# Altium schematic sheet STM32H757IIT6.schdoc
size 292 x 304 mm
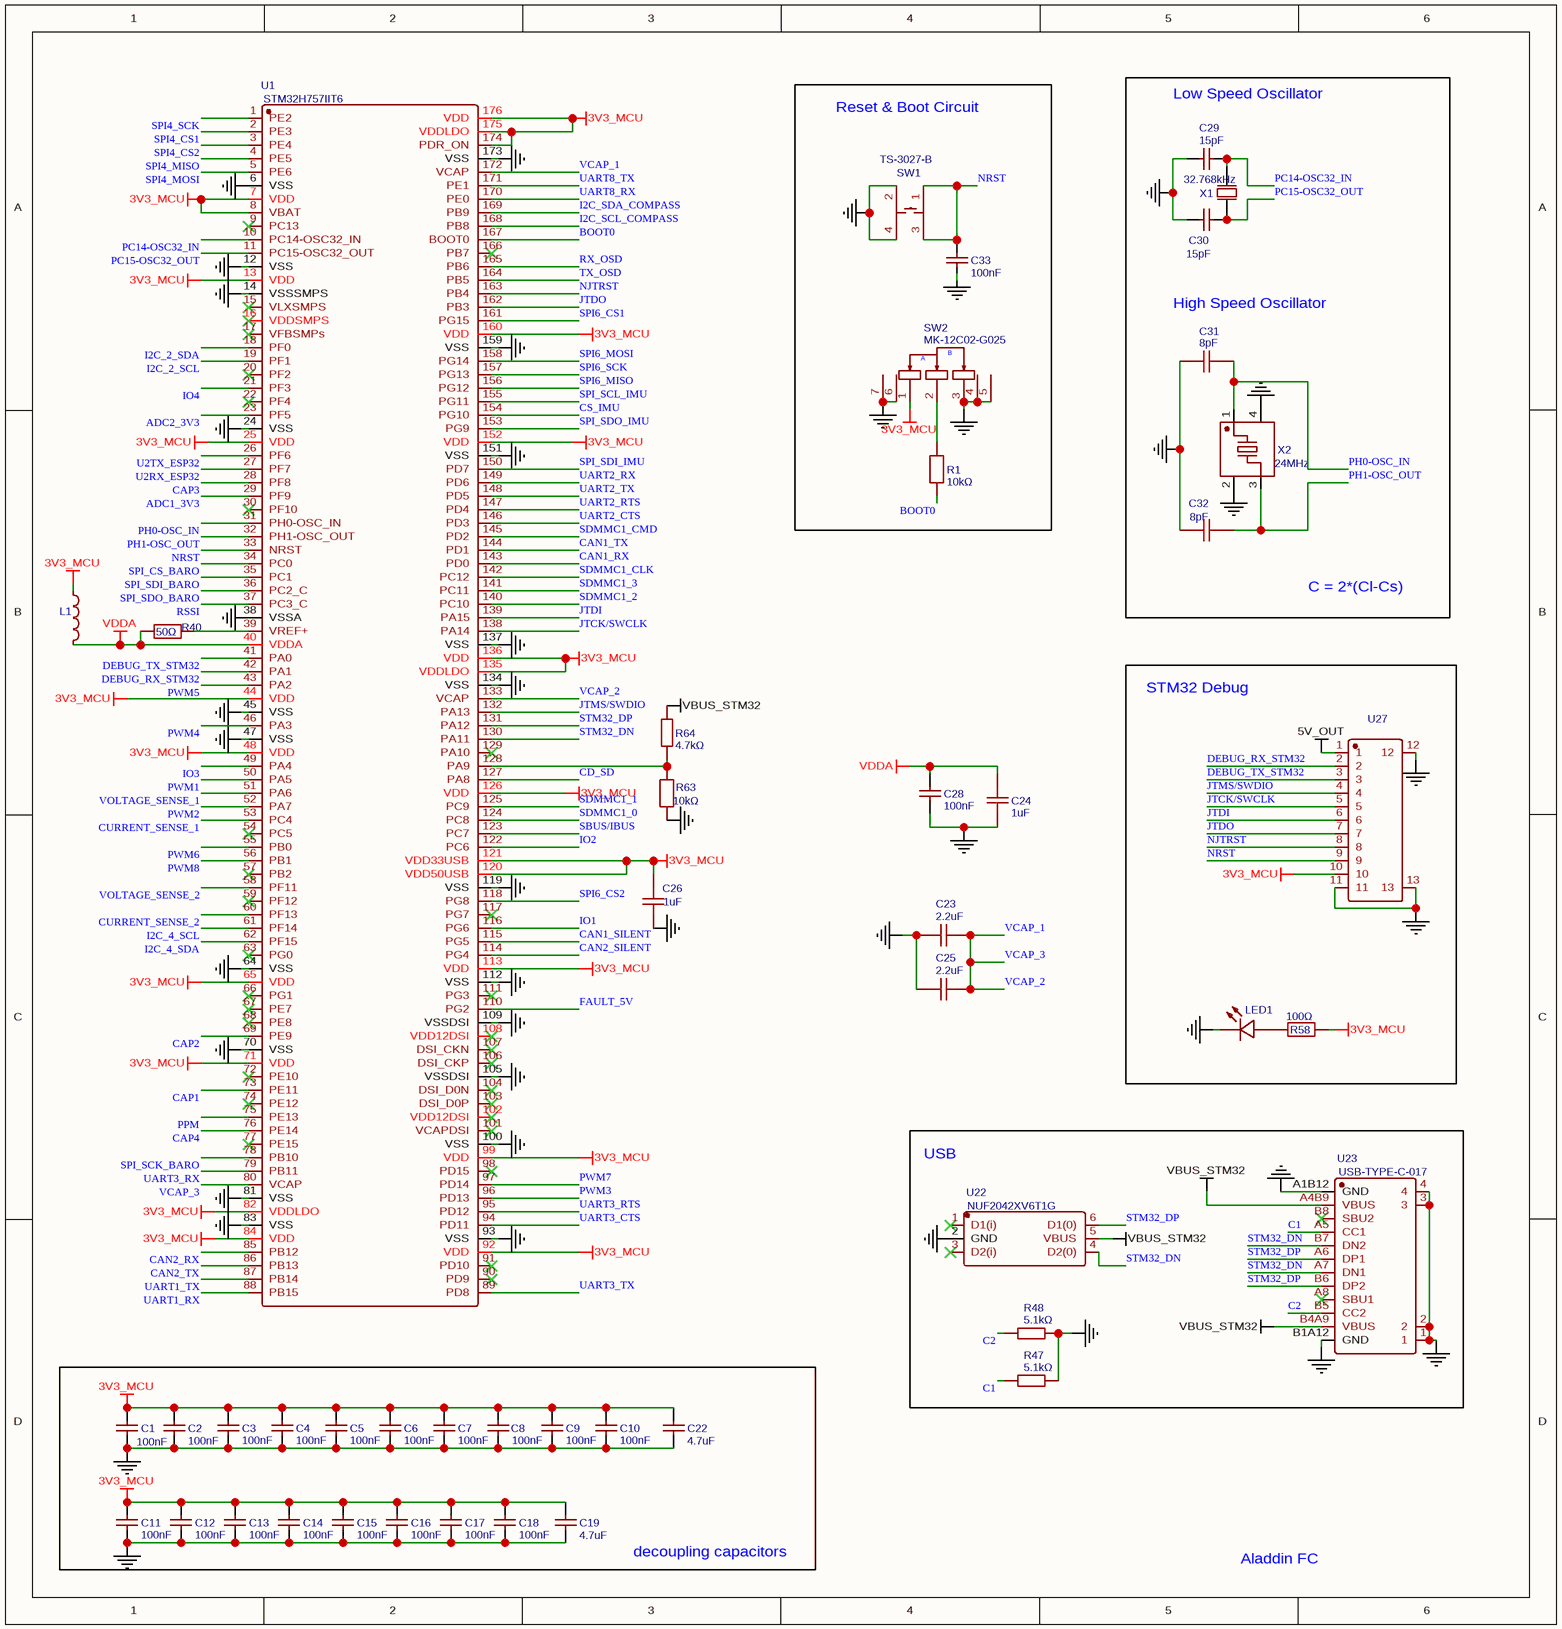
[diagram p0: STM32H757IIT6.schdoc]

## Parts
C1  100nF  [C0805]
C2  100nF  [C0805]
C3  100nF  [C0805]
C4  100nF  [C0805]
C5  100nF  [C0805]
C6  100nF  [C0805]
C7  100nF  [C0805]
C8  100nF  [C0805]
C9  100nF  [C0805]
C10  100nF  [C0805]
C11  100nF  [C0805]
C12  100nF  [C0805]
C13  100nF  [C0805]
C14  100nF  [C0805]
C15  100nF  [C0805]
C16  100nF  [C0805]
C17  100nF  [C0805]
C18  100nF  [C0805]
C19  4.7uF  [C0805]
C22  4.7uF  [C0805]
C23  2.2uF  [C0805]
C24  1uF  [C0805]
C25  2.2uF  [C0805]
C26  1uF  [C0805]
C28  100nF  [C0805]
C29  15pF  [C0603]
C30  15pF  [C0603]
C31  8pF  [C0805]
C32  8pF  [C0805]
C33  100nF  [C0805]
L1  FCM1005KF-601T03  [L0402]  (value not drawn)
LED1  SZYY0805B  [LED0805-R-RD_BLUE]  (value not drawn)
R1  10kΩ  [R0805]
R40  50Ω  [R0805]
R47  5.1kΩ  [R0402]
R48  5.1kΩ  [R0402]
R58  100Ω  [R0603]
R63  10kΩ  [R0805]
R64  4.7kΩ  [R0805]
SW1  TS-3027-B  [SW-SMD_4P-L3.0-W2.8-P1.65-TL_GT-TS171A-H014-L1]
SW2  MK-12C02-G025  [SW-SMD_MK-12C02-G025]
U1  STM32H757IIT6  [LQFP-176_L24.0-W24.0-P0.50-LS26.0-BL]
U22  NUF2042XV6T1G  [SOT-563_L1.6-W1.2-P0.50-LS1.6-TL]
U23  USB-TYPE-C-017  [USB-TYPE-C-SMD_C9900008089_ALA1]
U27  A1257WR-S-11P  [CONN-SMD_A1257WR-S-11P]  (value not drawn)
X1  32.768kHz  [OSC-SMD_2P-L3.2-W1.5]
X2  24MHz  [OSC-SMD_4P-L2.0-W1.6-BL]

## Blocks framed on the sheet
Reset & Boot Circuit: C33 R1 SW1 SW2
STM32 Debug: LED1 R58 U27
USB: R47 R48 U22 U23
decoupling capacitors: C1-C19 C22

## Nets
3V3_MCU: C1.1 C2.2 C3.2 C4.2 C5.2 C6.2 C7.1 C8.2 C9.2 C10.2 C11.1 C12.2 C13.2 C14.2 C15.2 C16.2 C17.1 C18.2 C19.2 C22.2 C26.1 L1.1 R58.2 SW2.1 U1.7(VDD) U1.8(VBAT) U1.13(VDD) U1.25(VDD) U1.44(VDD) U1.48(VDD) U1.65(VDD) U1.71(VDD) U1.82(VDDLDO) U1.84(VDD) U1.92(VDD) U1.99(VDD) U1.113(VDD) U1.120(VDD50USB) U1.121(VDD33USB) U1.126(VDD) U1.135(VDDLDO) U1.136(VDD) U1.152(VDD) U1.160(VDD) U1.174(PDR_ON) U1.175(VDDLDO) U1.176(VDD) U27.10
5V_OUT: U27.1
GND: C1.2 C2.1 C3.1 C4.1 C5.1 C6.1 C7.2 C8.1 C9.1 C10.1 C11.2 C12.1 C13.1 C14.1 C15.1 C16.1 C17.2 C18.1 C19.1 C22.1 C23.1 C24.2 C25.1 C26.2 C28.2 C29.1 C30.1 C31.1 C32.1 C33.1 LED1.2(-) R47.2 R48.2 R63.1 SW1.2 SW1.4 SW2.3 SW2.4 SW2.5 SW2.6 SW2.7 U1.6(VSS) U1.12(VSS) U1.14(VSSSMPS) U1.24(VSS) U1.38(VSSA) U1.45(VSS) U1.47(VSS) U1.64(VSS) U1.70(VSS) U1.81(VSS) U1.83(VSS) U1.93(VSS) U1.100(VSS) U1.105(VSSDSI) U1.109(VSSDSI) U1.112(VSS) U1.119(VSS) U1.134(VSS) U1.137(VSS) U1.151(VSS) U1.159(VSS) U1.173(VSS) U22.2(GND) U23.1 U23.2 U23.3 U23.4 U23.A1B12(GND) U23.B1A12(GND) U27.11 U27.12 U27.13 X2.2(GND) X2.4(GND)
VBUS_STM32: R64.2 U22.5(VBUS) U23.A4B9(VBUS) U23.B4A9(VBUS)
VDDA: C24.1 C28.1 L1.2 R40.1 U1.40(VDDA)
ADC1_3V3: U1.29(PF9)
ADC2_3V3: U1.23(PF5)
BOOT0: R1.1 U1.167(BOOT0)
C1: R47.1 U23.A5(CC1)
C2: R48.1 U23.B5(CC2)
CAN1_RX: U1.143(PD0)
CAN1_SILENT: U1.115(PG5)
CAN1_TX: U1.144(PD1)
CAN2_RX: U1.85(PB12)
CAN2_SILENT: U1.114(PG4)
CAN2_TX: U1.86(PB13)
CAP1: U1.73(PE11)
CAP2: U1.69(PE9)
CAP3: U1.28(PF8)
CAP4: U1.76(PE14)
CD_SD: U1.127(PA8)
CS_IMU: U1.154(PG10)
CURRENT_SENSE_1: U1.53(PC4)
CURRENT_SENSE_2: U1.60(PF13)
DEBUG_RX_STM32: U1.42(PA1) U27.2
DEBUG_TX_STM32: U1.41(PA0) U27.3
FAULT_5V: U1.110(PG2)
I2C_2_SCL: U1.19(PF1)
I2C_2_SDA: U1.18(PF0)
I2C_4_SCL: U1.61(PF14)
I2C_4_SDA: U1.62(PF15)
I2C_SCL_COMPASS: U1.168(PB8)
I2C_SDA_COMPASS: U1.169(PB9)
IO1: U1.116(PG6)
IO2: U1.122(PC6)
IO3: U1.49(PA4)
IO4: U1.21(PF3)
JTCK/SWCLK: U1.138(PA14) U27.5
JTDI: U1.139(PA15) U27.6
JTDO: U1.162(PB3) U27.7
JTMS/SWDIO: U1.132(PA13) U27.4
NJTRST: U1.163(PB4) U27.8
NRST: C33.2 SW1.1 SW1.3 U1.33(NRST) U27.9
PC14-OSC32_IN: C29.2 U1.10(PC14-OSC32_IN) X1.2(OSC2)
PC15-OSC32_OUT: C30.2 U1.11(PC15-OSC32_OUT) X1.1(OSC1)
PH0-OSC_IN: C31.2 U1.31(PH0-OSC_IN) X2.1
PH1-OSC_OUT: C32.2 U1.32(PH1-OSC_OUT) X2.3
PPM: U1.75(PE13)
PWM1: U1.50(PA5)
PWM2: U1.52(PA7)
PWM3: U1.96(PD13)
PWM4: U1.46(PA3)
PWM5: U1.43(PA2)
PWM6: U1.55(PB0)
PWM7: U1.97(PD14)
PWM8: U1.56(PB1)
RSSI: U1.37(PC3_C)
RX_OSD: U1.165(PB6)
SBUS/IBUS: U1.123(PC7)
SDMMC1_0: U1.124(PC8)
SDMMC1_1: U1.125(PC9)
SDMMC1_2: U1.140(PC10)
SDMMC1_3: U1.141(PC11)
SDMMC1_CLK: U1.142(PC12)
SDMMC1_CMD: U1.145(PD2)
SPI4_CS1: U1.2(PE3)
SPI4_CS2: U1.3(PE4)
SPI4_MISO: U1.4(PE5)
SPI4_MOSI: U1.5(PE6)
SPI4_SCK: U1.1(PE2)
SPI6_CS1: U1.161(PG15)
SPI6_CS2: U1.118(PG8)
SPI6_MISO: U1.156(PG12)
SPI6_MOSI: U1.158(PG14)
SPI6_SCK: U1.157(PG13)
SPI_CS_BARO: U1.34(PC0)
SPI_SCK_BARO: U1.78(PB10)
SPI_SCL_IMU: U1.155(PG11)
SPI_SDI_BARO: U1.35(PC1)
SPI_SDI_IMU: U1.150(PD7)
SPI_SDO_BARO: U1.36(PC2_C)
SPI_SDO_IMU: U1.153(PG9)
STM32_DN: U1.130(PA11) U22.4(D2(0)) U23.A7(DN1) U23.B7(DN2)
STM32_DP: U1.131(PA12) U22.6(D1(0)) U23.A6(DP1) U23.B6(DP2)
TX_OSD: U1.164(PB5)
U2RX_ESP32: U1.27(PF7)
U2TX_ESP32: U1.26(PF6)
UART1_RX: U1.88(PB15)
UART1_TX: U1.87(PB14)
UART2_CTS: U1.146(PD3)
UART2_RTS: U1.147(PD4)
UART2_RX: U1.149(PD6)
UART2_TX: U1.148(PD5)
UART3_CTS: U1.94(PD11)
UART3_RTS: U1.95(PD12)
UART3_RX: U1.79(PB11)
UART3_TX: U1.89(PD8)
UART8_RX: U1.170(PE0)
UART8_TX: U1.171(PE1)
VCAP_1: C23.2 C25.2 U1.80(VCAP) U1.133(VCAP) U1.172(VCAP)  [also labelled VCAP_2, VCAP_3]
VOLTAGE_SENSE_1: U1.51(PA6)
VOLTAGE_SENSE_2: U1.58(PF11)
NetLED1_1: LED1.1(+) R58.1
NetR1_2: R1.2 SW2.2
NetR40_2: R40.2 U1.39(VREF+)
NetR63_2: R63.2 R64.1 U1.128(PA9)

Not connected (* = marked no-connect by the designer): U1 9(PC13)* 15(VLXSMPS)* 16(VDDSMPS)* 17(VFBSMPs)* 20(PF2)* 22(PF4)* 30(PF10)* 54(PC5)* 57(PB2)* 59(PF12)* 63(PG0)* 66(PG1)* 67(PE7)* 68(PE8)* 72(PE10)* 74(PE12)* 77(PE15)* 90(PD9)* 91(PD10)* 98(PD15)* 101(VCAPDSI)* 102(VDD12DSI)* 103(DSI_D0P)* 104(DSI_D0N)* 106(DSI_CKP)* 107(DSI_CKN)* 108(VDD12DSI)* 111(PG3)* 117(PG7)* 129(PA10)* 166(PB7)*; U22 1(D1(i))* 3(D2(i))*; U23 A8(SBU1)* B8(SBU2)*

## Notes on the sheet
- Low Speed Oscillator
- High Speed Oscillator
- C = 2*(Cl-Cs)
- Aladdin FC

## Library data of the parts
C1-C18 C28 C33 = 100nF: BOM_Manufacturer Part: CL21B104KBCNNNC; BOM_Manufacturer: SAMSUNG; nameAlias: Capacitance
C19 C22 = 4.7uF: BOM_Manufacturer: SAMSUNG; BOM_Manufacturer Part: CL21B475KAFNNNE; nameAlias: Capacitance
C23 C25 = 2.2uF: BOM_Manufacturer: Samwha Capacitor; BOM_Manufacturer Part: CS2012X5R225K500NRE; nameAlias: Capacitance; Contributor: LCSC
C24 C26 = 1uF: BOM_Manufacturer: Taiyo Yuden; BOM_Manufacturer Part: UMK212BJ105KG-T; nameAlias: Capacitance; Contributor: LCSC
C29 C30 = 15pF: BOM_Manufacturer Part: CL10C150JB8NNNC; BOM_Manufacturer: SAMSUNG; nameAlias: Capacitance
C31 C32 = 8pF: BOM_Manufacturer: Samsung Electro-Mechanics; BOM_Manufacturer Part: CL21C080DBANNNC; nameAlias: Capacitance; Contributor: LCSC
L1 = FCM1005KF-601T03: BOM_Manufacturer: TAI-TECH(台庆); Contributor: LCSC
LED1 = SZYY0805B: BOM_Manufacturer: yongyu(永裕光电); Contributor: LCSC
R1 R63 = 10kΩ: BOM_Manufacturer: Viking Tech; BOM_Manufacturer Part: ARG05BTC1002; Resistance (Ohms): 10K; nameAlias: Resistance; Contributor: LCSC
R40 = 50Ω: BOM_Manufacturer: 光颉(Viking); BOM_Manufacturer Part: ARG05FTC0500; nameAlias: Resistance; Contributor: LCSC
R47 R48 = 5.1kΩ: BOM_Manufacturer: Tyohm; BOM_Manufacturer Part: RMC04025.1K5%N; Resistance (Ohms): 5.1K; nameAlias: Resistance; Contributor: LCSC
R58 = 100Ω: BOM_Manufacturer: FOJAN(富捷); BOM_Manufacturer Part: FRC0603J101 TS; nameAlias: Resistance; Contributor: lcsc
R64 = 4.7kΩ: BOM_Manufacturer: Tyohm; BOM_Manufacturer Part: RMC08054.7K1%N; Resistance (Ohms): 4.7K; nameAlias: Resistance; Contributor: LCSC
SW1 = TS-3027-B: BOM_Manufacturer: XKB Enterprise; Contributor: LCSC
SW2 = MK-12C02-G025: BOM_Manufacturer: G-Switch; Contributor: LCSC
U1 = STM32H757IIT6: BOM_Manufacturer: STMicroelectronics; Contributor: LCSC
U22 = NUF2042XV6T1G: BOM_Manufacturer: ON Semicon; Contributor: LCSC
U23 = USB-TYPE-C-017: BOM_Manufacturer: DEALON(德艺隆); Contributor: lcsc
U27 = A1257WR-S-11P: BOM_Manufacturer: Changjiang Connectors; Contributor: LCSC
X1 = 32.768kHz: BOM_Manufacturer: CITIZEN; BOM_Manufacturer Part: CM315D32768DZFT; nameAlias: Frequency; Contributor: LCSC
X2 = 24MHz: BOM_Manufacturer: TST; BOM_Manufacturer Part: TZ1620C; nameAlias: Frequency; Contributor: LCSC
